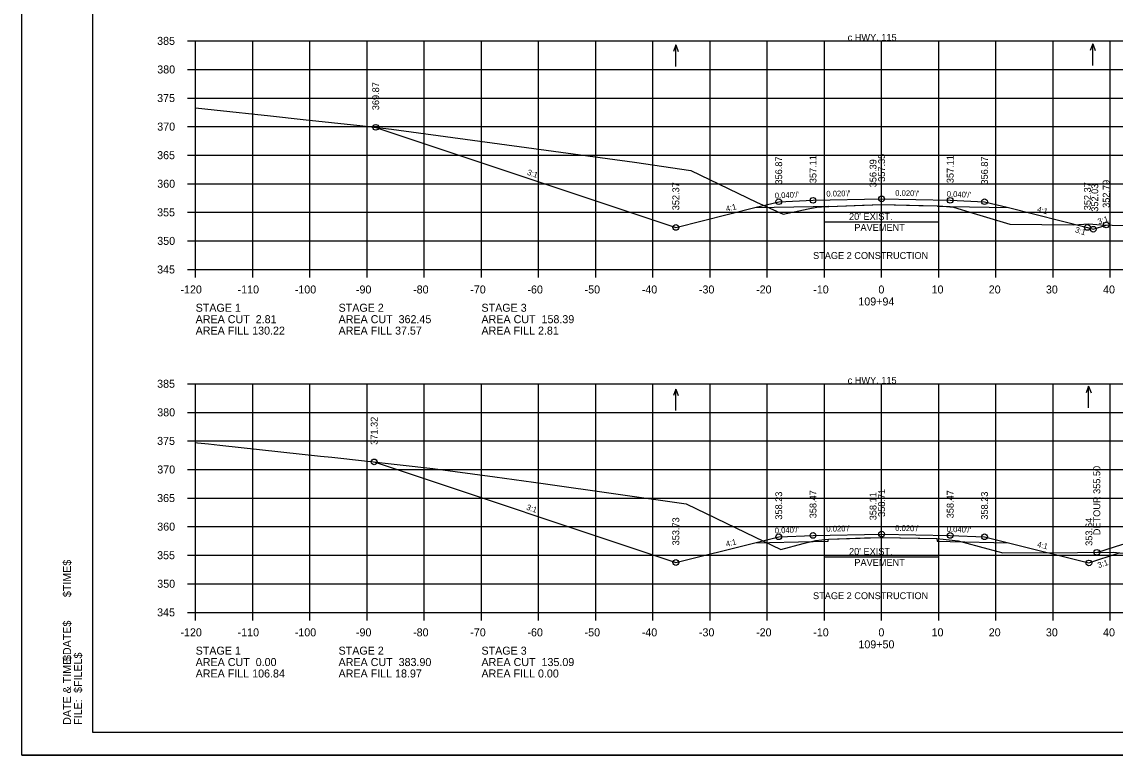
# Model space of a CAD drawing. Extents: x 1630712 to 1632516, y 782146 to 785403.
# Drawn here: x 1632182.6 to 1632373.8, y 783910 to 784038.3 of the extents above; entities that cross this region are included whole.
import ezdxf

# ---------------------------------------------------------------- set-up
doc = ezdxf.new("R2010")
doc.units = 0
for name, color, linetype in [('Default', 7, 'Continuous'), ('Notes', 7, 'Continuous'), ('R_Alt Surface', 7, 'Continuous'), ('R_Axis', 7, 'Continuous'), ('R_Axis Annot', 7, 'Continuous'), ('R_Border', 7, 'Continuous'), ('R_Detour Surface', 7, 'Continuous'), ('R_Exist Surface', 7, 'Continuous'), ('R_Fin Surface', 7, 'Continuous'), ('R_Grid', 7, 'Continuous'), ('R_No Plot', 7, 'Continuous'), ('R_Water Annot', 7, 'Continuous'), ('R_Xsect Elev', 7, 'Continuous'), ('R_Xsect Elev Detour', 7, 'Continuous'), ('R_Xsect Slope', 7, 'Continuous')]:
    doc.layers.add(name, color=color, linetype=linetype)

msp = doc.modelspace()

# ---------------------------------------------------------------- linework, layer by layer
at = {"layer": 'Notes'}
for p, q in [((1632322.96, 784001.57), (1632322.96, 784004.97)), ((1632342.96, 784001.57), (1632342.96, 784004.97)), ((1632322.96, 784003.27), (1632342.96, 784003.27)), ((1632322.96, 783942.95), (1632322.96, 783946.35)), ((1632322.96, 783944.65), (1632342.96, 783944.65)), ((1632342.96, 783942.95), (1632342.96, 783946.35))]:
    msp.add_line(p, q, dxfattribs=at)
at = {"layer": 'R_Alt Surface'}
for points in [[(1632310.79, 784005.78), (1632320.96, 784005.98), (1632323.66, 784006.04), (1632323.71, 784005.99), (1632332.97, 784006.34), (1632342.69, 784006.11), (1632342.74, 784006.03), (1632344.96, 784005.98), (1632355.14, 784005.78)], [(1632310.79, 783947.14), (1632320.96, 783947.34), (1632323.6, 783947.39), (1632323.65, 783947.77), (1632332.86, 783948.07), (1632342.61, 783947.87), (1632342.66, 783947.39), (1632344.96, 783947.34), (1632355.14, 783947.14)]]:
    msp.add_lwpolyline(points, dxfattribs=at)
at = {"layer": 'R_Axis'}
for p, q in [((1632211.56, 784034.96), (1632212.96, 784034.96)), ((1632212.96, 783994.96), (1632212.96, 784034.96)), ((1632211.56, 784029.96), (1632212.96, 784029.96)), ((1632211.56, 784024.96), (1632212.96, 784024.96)), ((1632211.56, 784019.96), (1632212.96, 784019.96)), ((1632211.56, 784014.96), (1632212.96, 784014.96)), ((1632211.56, 784009.96), (1632212.96, 784009.96)), ((1632211.56, 784004.96), (1632212.96, 784004.96)), ((1632211.56, 783999.96), (1632212.96, 783999.96)), ((1632211.56, 783994.96), (1632212.96, 783994.96)), ((1632212.96, 783994.96), (1632492.96, 783994.96)), ((1632212.96, 783993.56), (1632212.96, 783994.96)), ((1632222.96, 783993.56), (1632222.96, 783994.96)), ((1632232.96, 783993.56), (1632232.96, 783994.96)), ((1632242.96, 783993.56), (1632242.96, 783994.96)), ((1632252.96, 783993.56), (1632252.96, 783994.96)), ((1632262.96, 783993.56), (1632262.96, 783994.96)), ((1632272.96, 783993.56), (1632272.96, 783994.96)), ((1632282.96, 783993.56), (1632282.96, 783994.96)), ((1632292.96, 783993.56), (1632292.96, 783994.96)), ((1632302.96, 783993.56), (1632302.96, 783994.96)), ((1632312.96, 783993.56), (1632312.96, 783994.96)), ((1632322.96, 783993.56), (1632322.96, 783994.96)), ((1632332.96, 783993.56), (1632332.96, 783994.96)), ((1632342.96, 783993.56), (1632342.96, 783994.96)), ((1632352.96, 783993.56), (1632352.96, 783994.96)), ((1632362.96, 783993.56), (1632362.96, 783994.96)), ((1632372.96, 783993.56), (1632372.96, 783994.96)), ((1632211.56, 783974.96), (1632212.96, 783974.96)), ((1632212.96, 783934.96), (1632212.96, 783974.96)), ((1632211.56, 783969.96), (1632212.96, 783969.96)), ((1632211.56, 783964.96), (1632212.96, 783964.96)), ((1632211.56, 783959.96), (1632212.96, 783959.96)), ((1632211.56, 783954.96), (1632212.96, 783954.96)), ((1632211.56, 783949.96), (1632212.96, 783949.96)), ((1632211.56, 783944.96), (1632212.96, 783944.96)), ((1632211.56, 783939.96), (1632212.96, 783939.96)), ((1632211.56, 783934.96), (1632212.96, 783934.96)), ((1632212.96, 783934.96), (1632492.96, 783934.96)), ((1632212.96, 783933.56), (1632212.96, 783934.96)), ((1632222.96, 783933.56), (1632222.96, 783934.96)), ((1632232.96, 783933.56), (1632232.96, 783934.96)), ((1632242.96, 783933.56), (1632242.96, 783934.96)), ((1632252.96, 783933.56), (1632252.96, 783934.96)), ((1632262.96, 783933.56), (1632262.96, 783934.96)), ((1632272.96, 783933.56), (1632272.96, 783934.96)), ((1632282.96, 783933.56), (1632282.96, 783934.96)), ((1632292.96, 783933.56), (1632292.96, 783934.96)), ((1632302.96, 783933.56), (1632302.96, 783934.96)), ((1632312.96, 783933.56), (1632312.96, 783934.96)), ((1632322.96, 783933.56), (1632322.96, 783934.96)), ((1632332.96, 783933.56), (1632332.96, 783934.96)), ((1632342.96, 783933.56), (1632342.96, 783934.96)), ((1632352.96, 783933.56), (1632352.96, 783934.96)), ((1632362.96, 783933.56), (1632362.96, 783934.96)), ((1632372.96, 783933.56), (1632372.96, 783934.96))]:
    msp.add_line(p, q, dxfattribs=at)
at = {"layer": 'R_Border'}
for p, q in [((1632194.96, 783913.96), (1632194.96, 784119.42)), ((1632511.14, 783913.96), (1632194.96, 783913.96))]:
    msp.add_line(p, q, dxfattribs=at)
at = {"layer": 'R_Detour Surface'}
msp.add_lwpolyline([(1632370.61, 783945.46), (1632373.86, 783946.47), (1632374.78, 783946.75), (1632377.41, 783947.56), (1632378.11, 783947.78), (1632379.49, 783947.78), (1632380.19, 783947.79), (1632390.6, 783947.87), (1632390.61, 783947.87), (1632399.39, 783947.69), (1632401.02, 783947.66), (1632402.74, 783947.63), (1632403.1, 783947.63), (1632403.83, 783947.39), (1632406.3, 783946.57), (1632406.53, 783946.49), (1632406.92, 783946.36), (1632415.39, 783943.56), (1632417.28, 783942.94)], dxfattribs=at)
at = {"layer": 'R_Exist Surface'}
for points in [[(1632212.96, 784023.23), (1632216.18, 784022.88), (1632226.03, 784021.82), (1632231.79, 784021.19), (1632241.7, 784020.13), (1632247.23, 784019.52), (1632289.75, 784013.72), (1632299.57, 784012.26), (1632311.1, 784006.75), (1632315.73, 784004.64), (1632320.1, 784005.58), (1632321.6, 784005.88), (1632322.46, 784005.91), (1632323.71, 784005.99), (1632329.64, 784006.22), (1632332.97, 784006.34), (1632339.47, 784006.18), (1632342.69, 784006.11), (1632343.69, 784006.01), (1632345.52, 784005.84), (1632348.95, 784004.82), (1632355.38, 784002.88), (1632366.57, 784002.76), (1632369.19, 784002.93), (1632371.32, 784002.77), (1632373.29, 784002.71), (1632392.65, 784002.21)], [(1632212.96, 783964.68), (1632213.28, 783964.65), (1632215.19, 783964.44), (1632217.17, 783964.23), (1632234.82, 783962.3), (1632236.78, 783962.09), (1632254.46, 783960.15), (1632265.27, 783958.68), (1632273.74, 783957.49), (1632298.76, 783953.97), (1632309.15, 783948.94), (1632315.33, 783945.97), (1632319.21, 783947.02), (1632321.39, 783947.56), (1632322.5, 783947.65), (1632323.65, 783947.77), (1632329.95, 783947.97), (1632332.86, 783948.07), (1632339.62, 783947.94), (1632342.61, 783947.87), (1632343.72, 783947.76), (1632346.37, 783947.49), (1632351.55, 783946.09), (1632354.19, 783945.35), (1632367.25, 783945.45), (1632373.51, 783945.47), (1632386.83, 783944.09)]]:
    msp.add_lwpolyline(points, dxfattribs=at)
at = {"layer": 'R_Fin Surface'}
for points in [[(1632244.46, 784019.83), (1632296.96, 784002.32), (1632310.79, 784005.78), (1632314.96, 784006.82), (1632320.96, 784007.06), (1632332.96, 784007.3), (1632344.96, 784007.06), (1632350.96, 784006.82), (1632355.14, 784005.78), (1632368.96, 784002.32), (1632369.98, 784001.99), (1632372.25, 784002.74)], [(1632244.19, 783961.28), (1632296.96, 783943.68), (1632310.79, 783947.14), (1632314.96, 783948.18), (1632320.96, 783948.42), (1632332.96, 783948.66), (1632344.96, 783948.42), (1632350.96, 783948.18), (1632355.14, 783947.14), (1632368.96, 783943.68), (1632369.23, 783943.6), (1632374.53, 783945.36)]]:
    msp.add_lwpolyline(points, dxfattribs=at)
at = {"layer": 'R_Grid'}
for p, q in [((1632212.96, 784034.96), (1632492.96, 784034.96)), ((1632212.96, 783994.96), (1632212.96, 784034.96)), ((1632222.96, 783994.96), (1632222.96, 784034.96)), ((1632232.96, 783994.96), (1632232.96, 784034.96)), ((1632242.96, 783994.96), (1632242.96, 784034.96)), ((1632252.96, 783994.96), (1632252.96, 784034.96)), ((1632262.96, 783994.96), (1632262.96, 784034.96)), ((1632272.96, 783994.96), (1632272.96, 784034.96)), ((1632282.96, 783994.96), (1632282.96, 784034.96)), ((1632292.96, 783994.96), (1632292.96, 784034.96)), ((1632302.96, 783994.96), (1632302.96, 784034.96)), ((1632312.96, 783994.96), (1632312.96, 784034.96)), ((1632322.96, 783994.96), (1632322.96, 784034.96)), ((1632332.96, 783994.96), (1632332.96, 784034.96)), ((1632342.96, 783994.96), (1632342.96, 784034.96)), ((1632352.96, 783994.96), (1632352.96, 784034.96)), ((1632362.96, 783994.96), (1632362.96, 784034.96)), ((1632372.96, 783994.96), (1632372.96, 784034.96)), ((1632212.96, 784029.96), (1632492.96, 784029.96)), ((1632212.96, 784024.96), (1632492.96, 784024.96)), ((1632212.96, 784019.96), (1632492.96, 784019.96)), ((1632212.96, 784014.96), (1632492.96, 784014.96)), ((1632212.96, 784009.96), (1632492.96, 784009.96)), ((1632212.96, 784004.96), (1632492.96, 784004.96)), ((1632212.96, 783999.96), (1632492.96, 783999.96)), ((1632212.96, 783994.96), (1632492.96, 783994.96)), ((1632212.96, 783974.96), (1632492.96, 783974.96)), ((1632212.96, 783934.96), (1632212.96, 783974.96)), ((1632222.96, 783934.96), (1632222.96, 783974.96)), ((1632232.96, 783934.96), (1632232.96, 783974.96)), ((1632242.96, 783934.96), (1632242.96, 783974.96)), ((1632252.96, 783934.96), (1632252.96, 783974.96)), ((1632262.96, 783934.96), (1632262.96, 783974.96)), ((1632272.96, 783934.96), (1632272.96, 783974.96)), ((1632282.96, 783934.96), (1632282.96, 783974.96)), ((1632292.96, 783934.96), (1632292.96, 783974.96)), ((1632302.96, 783934.96), (1632302.96, 783974.96)), ((1632312.96, 783934.96), (1632312.96, 783974.96)), ((1632322.96, 783934.96), (1632322.96, 783974.96)), ((1632332.96, 783934.96), (1632332.96, 783974.96)), ((1632342.96, 783934.96), (1632342.96, 783974.96)), ((1632352.96, 783934.96), (1632352.96, 783974.96)), ((1632362.96, 783934.96), (1632362.96, 783974.96)), ((1632372.96, 783934.96), (1632372.96, 783974.96)), ((1632212.96, 783969.96), (1632492.96, 783969.96)), ((1632212.96, 783964.96), (1632492.96, 783964.96)), ((1632212.96, 783959.96), (1632492.96, 783959.96)), ((1632212.96, 783954.96), (1632492.96, 783954.96)), ((1632212.96, 783949.96), (1632492.96, 783949.96)), ((1632212.96, 783944.96), (1632492.96, 783944.96)), ((1632212.96, 783939.96), (1632492.96, 783939.96)), ((1632212.96, 783934.96), (1632492.96, 783934.96))]:
    msp.add_line(p, q, dxfattribs=at)
at = {"layer": 'R_No Plot'}
msp.add_line((1632182.56, 783909.98), (1632515.9, 783909.98), dxfattribs=at)
msp.add_lwpolyline([(1632182.56, 784123.31), (1632515.9, 784123.31), (1632515.9, 783909.97), (1632182.56, 783909.97)], close=True, dxfattribs=at)
for centre in [(1632244.46, 784019.83), (1632332.96, 784007.3), (1632314.96, 784006.82), (1632320.96, 784007.06), (1632344.96, 784007.06), (1632350.96, 784006.82), (1632296.96, 784002.32), (1632296.96, 784002.32), (1632368.96, 784002.32), (1632369.98, 784001.99), (1632372.25, 784002.74), (1632244.19, 783961.28), (1632314.96, 783948.18), (1632320.96, 783948.42), (1632332.96, 783948.66), (1632344.96, 783948.42), (1632350.96, 783948.18), (1632370.61, 783945.46), (1632296.96, 783943.68), (1632296.96, 783943.68), (1632369.23, 783943.6)]:
    msp.add_circle(centre, 0.5, dxfattribs=at)
at = {"layer": 'R_Water Annot'}
for p, q in [((1632369.89, 784034.43), (1632369.47, 784033.27)), ((1632369.89, 784030.66), (1632369.89, 784034.43)), ((1632369.89, 784034.43), (1632370.31, 784033.27)), ((1632296.96, 784034.26), (1632296.54, 784033.1)), ((1632296.96, 784030.49), (1632296.96, 784034.26)), ((1632296.96, 784034.26), (1632297.38, 784033.1)), ((1632296.96, 783974.04), (1632296.54, 783972.89)), ((1632296.96, 783970.27), (1632296.96, 783974.04)), ((1632296.96, 783974.04), (1632297.38, 783972.89)), ((1632369.17, 783974.53), (1632368.75, 783973.38)), ((1632369.17, 783970.76), (1632369.17, 783974.53)), ((1632369.17, 783974.53), (1632369.59, 783973.38))]:
    msp.add_line(p, q, dxfattribs=at)

# ---------------------------------------------------------------- texts
at = {"layer": 'Default'}
for s, height, p in [('$TIME$', 1.397, (1632191.16, 783937.63)), ('$DATE$', 1.397, (1632191.16, 783926.45)), ('DATE & TIME:', 1.3968, (1632191.16, 783915.28)), ('$FILEL$', 1.397, (1632193.08, 783920.86)), ('FILE: ', 1.397, (1632193.08, 783915.28))]:
    msp.add_text(s, height=height, rotation=90, dxfattribs=at).set_placement(p)
at = {"layer": 'Notes'}
for s, p in [('c HWY. 115', (1632327.02, 784034.96)), ("20' EXIST.", (1632327.26, 784003.63)), ('PAVEMENT', (1632328.19, 784001.71)), ('STAGE 2 CONSTRUCTION', (1632320.96, 783996.8)), ('c HWY. 115', (1632327.02, 783974.96)), ("20' EXIST.", (1632327.26, 783945.01)), ('PAVEMENT', (1632328.19, 783943.09)), ('STAGE 2 CONSTRUCTION', (1632320.96, 783937.27))]:
    msp.add_text(s, height=1.2, dxfattribs=at).set_placement(p)
at = {"layer": 'R_Axis'}
for p in [(1632212.96, 783994.96), (1632212.96, 783934.96)]:
    msp.add_text('-', height=0.0001, dxfattribs=at).set_placement(p)
at = {"layer": 'R_Axis Annot'}
for s, p in [('385', (1632206.22, 784034.26)), ('380', (1632206.24, 784029.26)), ('375', (1632206.22, 784024.26)), ('370', (1632206.24, 784019.26)), ('365', (1632206.22, 784014.26)), ('360', (1632206.24, 784009.26)), ('355', (1632206.22, 784004.26)), ('350', (1632206.24, 783999.26)), ('345', (1632206.22, 783994.26)), ('-120', (1632210.3, 783990.76)), ('-110', (1632220.3, 783990.76)), ('-100', (1632230.3, 783990.76)), ('-90', (1632241, 783990.76)), ('-80', (1632251, 783990.76)), ('-70', (1632261, 783990.76)), ('-60', (1632271, 783990.76)), ('-50', (1632281, 783990.76)), ('-40', (1632291, 783990.76)), ('-30', (1632301, 783990.76)), ('-20', (1632311, 783990.76)), ('-10', (1632321, 783990.76)), ('0', (1632332.4, 783990.76)), ('10', (1632341.7, 783990.76)), ('20', (1632351.7, 783990.76)), ('30', (1632361.7, 783990.76)), ('40', (1632371.7, 783990.76)), ('STAGE 1', (1632212.96, 783987.56)), ('STAGE 2', (1632237.96, 783987.56)), ('STAGE 3', (1632262.96, 783987.56)), ('109+94', (1632328.89, 783988.66)), ('AREA CUT  2.81', (1632212.96, 783985.56)), ('AREA CUT  362.45', (1632237.96, 783985.56)), ('AREA CUT  158.39', (1632262.96, 783985.56)), ('AREA FILL 130.22', (1632212.96, 783983.56)), ('AREA FILL 37.57', (1632237.96, 783983.56)), ('AREA FILL 2.81', (1632262.96, 783983.56)), ('385', (1632206.22, 783974.26)), ('380', (1632206.24, 783969.26)), ('375', (1632206.22, 783964.26)), ('370', (1632206.24, 783959.26)), ('365', (1632206.22, 783954.26)), ('360', (1632206.24, 783949.26)), ('355', (1632206.22, 783944.26)), ('350', (1632206.24, 783939.26)), ('345', (1632206.22, 783934.26)), ('-120', (1632210.3, 783930.76)), ('-110', (1632220.3, 783930.76)), ('-100', (1632230.3, 783930.76)), ('-90', (1632241, 783930.76)), ('-80', (1632251, 783930.76)), ('-70', (1632261, 783930.76)), ('-60', (1632271, 783930.76)), ('-50', (1632281, 783930.76)), ('-40', (1632291, 783930.76)), ('-30', (1632301, 783930.76)), ('-20', (1632311, 783930.76)), ('-10', (1632321, 783930.76)), ('0', (1632332.4, 783930.76)), ('10', (1632341.7, 783930.76)), ('20', (1632351.7, 783930.76)), ('30', (1632361.7, 783930.76)), ('40', (1632371.7, 783930.76)), ('109+50', (1632328.9, 783928.66)), ('STAGE 1', (1632212.96, 783927.56)), ('STAGE 2', (1632237.96, 783927.56)), ('STAGE 3', (1632262.96, 783927.56)), ('AREA CUT  0.00', (1632212.96, 783925.56)), ('AREA CUT  383.90', (1632237.96, 783925.56)), ('AREA CUT  135.09', (1632262.96, 783925.56)), ('AREA FILL 106.84', (1632212.96, 783923.56)), ('AREA FILL 18.97', (1632237.96, 783923.56)), ('AREA FILL 0.00', (1632262.96, 783923.56))]:
    msp.add_text(s, height=1.4, dxfattribs=at).set_placement(p)
at = {"layer": 'R_Xsect Elev'}
for s, p in [('369.87', (1632245.06, 784022.83)), ('356.87', (1632315.56, 784009.82)), ('357.11', (1632321.56, 784010.06)), ('356.39', (1632332.06, 784009.34)), ('357.35', (1632333.56, 784010.3)), ('357.11', (1632345.56, 784010.06)), ('356.87', (1632351.56, 784009.82)), ('352.37', (1632297.56, 784005.32)), ('352.37', (1632369.56, 784005.32)), ('352.03', (1632370.85, 784005.06)), ('352.79', (1632372.85, 784005.74)), ('371.32', (1632244.79, 783964.28)), ('358.23', (1632315.56, 783951.18)), ('358.47', (1632321.56, 783951.42)), ('358.71', (1632333.56, 783951.66)), ('358.47', (1632345.56, 783951.42)), ('358.23', (1632351.56, 783951.18)), ('358.11', (1632332.06, 783951.07)), ('353.73', (1632297.56, 783946.68)), ('353.64', (1632369.83, 783946.6))]:
    msp.add_text(s, height=1.2, rotation=90, dxfattribs=at).set_placement(p)
at = {"layer": 'R_Xsect Elev Detour'}
msp.add_text('DETOUR 355.50', height=1.2, rotation=90, dxfattribs=at).set_placement((1632371.21, 783948.46))
at = {"layer": 'R_Xsect Slope'}
for s, rotation, p in [('3:1', 341.5651, (1632270.87, 784011.55)), ("0.040'/'", 2.2906, (1632314.29, 784007.4)), ("0.020'/'", 1.1458, (1632323.3, 784007.71)), ("0.020'/'", 358.8542, (1632335.33, 784007.86)), ("0.040'/'", 357.7094, (1632344.34, 784007.69)), ('4:1', 14.0362, (1632305.84, 784005.06)), ('4:1', 345.9638, (1632360.09, 784005.06)), ('3:1', 18.4349, (1632370.96, 784002.84)), ('3:1', 341.5651, (1632366.71, 784001.51)), ('3:1', 341.5651, (1632270.73, 783952.95)), ("0.040'/'", 2.2906, (1632314.29, 783948.76)), ("0.020'/'", 1.1458, (1632323.3, 783949.07)), ("0.020'/'", 358.8542, (1632335.33, 783949.22)), ("0.040'/'", 357.7094, (1632344.34, 783949.05)), ('4:1', 14.0362, (1632305.84, 783946.42)), ('4:1', 345.9638, (1632360.09, 783946.42)), ('3:1', 18.4349, (1632370.93, 783942.69))]:
    msp.add_text(s, height=1, rotation=rotation, dxfattribs=at).set_placement(p)

doc.saveas('drawing.dxf')
